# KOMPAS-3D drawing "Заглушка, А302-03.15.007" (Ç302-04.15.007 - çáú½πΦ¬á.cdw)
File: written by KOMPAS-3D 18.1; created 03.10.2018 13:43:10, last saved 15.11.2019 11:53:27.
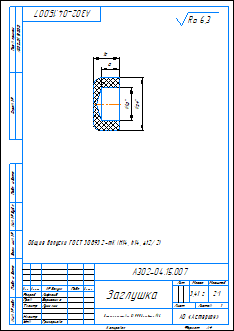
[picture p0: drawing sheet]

Sheet 1: A4, portrait

Document properties: Автор: Милов; Организация: Милов; Полное имя файла: D:\Мембранные насосы\Мембранный электропривод\А302-00.00.000 - ASTRA-302 (МЭ200)\А302-04.00.000 - Мембранный насос ASTRA-302-PP\А302-04.15.007 - Заглушка.cdw; Параметр неуказанной шероховатости: Ra 6,3; Масса: 0.00340597

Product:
- Part/product: Заглушка  | designation А302-03.15.007
    Масса: 0.00340597
    Раздел спецификации: Детали
    Форматы листов документа: A4
    source file: ..\Чертежи Полипропилен\А302-03.15.007 - Заглушка.cdw
- Part/product: Заглушка  | designation А302-01.15.007
    Масса: 0.00113785
    Раздел спецификации: Детали
    Форматы листов документа: A4
    source file: ..\3Д ПВХ\А302-01.15.007 - Заглушка.cdw

Title block, sheet 1: Наименование: Заглушка; designation: А302-04.15.007; Масса: 3,41 г; scale: 2:1; Количество листов документа: 1; organisation: АО «Астерион»; Форматы листов документа: A4; stored path: \\192.168.87.28\Konstructor_doc\Мембранные насосы\Мембранный электропривод\А302-00.00.000 - ASTRA-302 (МЭ200)\3Д ПВХ\А302-01.15.007 - Заглушка.cdw; Разработал: Лифлянд; Проверил: Борисенко; Т. контр.: Лучихин; Утвердил: Григорьева

Views: Вид 1, Местный разрез 1, Спереди, Проекционный вид 2
Referenced files in D:\Мембранные насосы\Мембранный электропривод\А302-00.00.000 - ASTRA-302 (МЭ200)\3Д ПВХ\: А302-01.15.007 - Заглушка.m3d
Referenced files in Z:\Мембранные насосы\Мембранный электропривод\А302-00.00.000 - ASTRA-302 (МЭ200)\3Д ПВХ\: А302-01.15.007 - Заглушка.m3d
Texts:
  Деталь заготовка FV PPR Заглушка  16
  Ra 6,3
Dimensions and other numbers on the sheet: 8; 12; 16; 24; 2:1; 1; 3,41 г

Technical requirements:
  Общие допуски ГОСТ 30893.2-mK (H14, h14,  t2/2).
